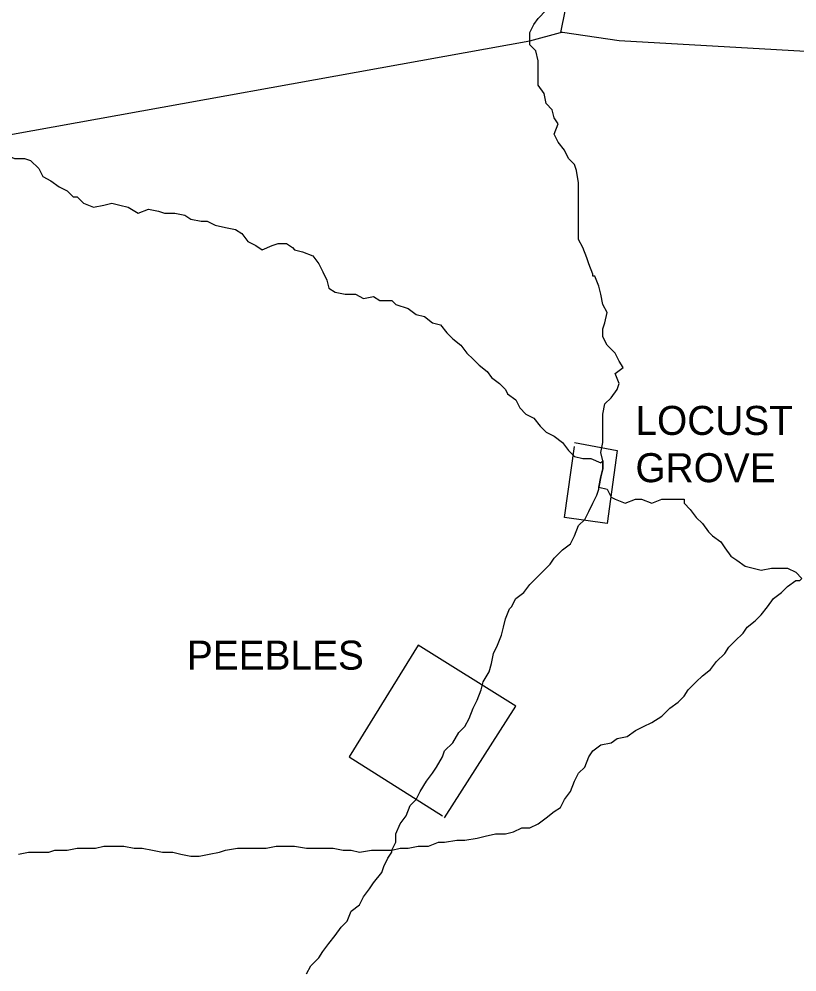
# Model space of a CAD drawing. Extents: x 0 to 34, y 0 to 22.
# Drawn here: x 4.319 to 4.841, y 17.195 to 17.836 of the extents above; entities that cross this region are included whole.
import ezdxf

# ---------------------------------------------------------------- set-up
doc = ezdxf.new("R2010")
doc.units = 0
doc.layers.add('Default', color=7, linetype='Continuous')

msp = doc.modelspace()

# ---------------------------------------------------------------- linework, layer by layer
at = {"layer": 'Default'}
for points in [[(4.80243, 18.46879), (4.77789, 18.33653), (4.75744, 18.21928), (4.74381, 18.1402), (4.72881, 18.05976), (4.71245, 17.97386), (4.68245, 17.82661)], [(4.662, 17.82116), (4.662, 17.82661), (4.66473, 17.83207), (4.66745, 17.83616), (4.67291, 17.84161), (4.677, 17.84707), (4.68245, 17.85116), (4.68245, 17.85661), (4.67972, 17.86206), (4.68245, 17.86752), (4.67836, 17.87297), (4.67836, 17.87979), (4.68109, 17.88524), (4.68245, 17.89206), (4.68245, 17.90024), (4.68245, 17.90433), (4.68245, 17.90433)], [(3.6667, 17.67937), (3.71715, 17.67664), (3.88212, 17.67118), (3.97347, 17.69027), (4.28433, 17.75299), (4.662, 17.82116), (4.68245, 17.82661)], [(4.70427, 17.66437), (4.70154, 17.67118), (4.70018, 17.67528), (4.69745, 17.68209), (4.69472, 17.68755), (4.69472, 17.69436), (4.69472, 17.70118), (4.69472, 17.708), (4.69472, 17.71345), (4.69472, 17.72027), (4.69472, 17.72572), (4.69336, 17.7339), (4.692, 17.73799), (4.68791, 17.74208), (4.68518, 17.74754), (4.68109, 17.75299), (4.67836, 17.75844), (4.68109, 17.76526), (4.67836, 17.76935), (4.677, 17.7748), (4.67291, 17.7789), (4.67154, 17.78571), (4.66745, 17.79117), (4.66745, 17.79526), (4.66745, 17.80207), (4.66745, 17.80753), (4.66609, 17.81434), (4.662, 17.81843), (4.662, 17.8198), (4.662, 17.82116)], [(4.93332, 17.80889), (4.72199, 17.82116), (4.68382, 17.82661), (4.68245, 17.82661)], [(4.2857, 17.75163), (4.29115, 17.75026), (4.29797, 17.7489), (4.30342, 17.74617), (4.30887, 17.74481), (4.31569, 17.74208), (4.32251, 17.74208), (4.3266, 17.74072), (4.33205, 17.73527), (4.33478, 17.72981), (4.34023, 17.72709), (4.34569, 17.72299), (4.35114, 17.72027), (4.35523, 17.71618), (4.35796, 17.71618)], [(4.35796, 17.71618), (4.36205, 17.71209), (4.36886, 17.70936), (4.37568, 17.71072), (4.38114, 17.71209), (4.38659, 17.71072), (4.39204, 17.70936), (4.39886, 17.70527), (4.40568, 17.708), (4.41249, 17.70663), (4.41658, 17.70527), (4.4234, 17.70527), (4.43022, 17.70391), (4.43431, 17.70118), (4.44113, 17.69982), (4.44522, 17.69982)], [(4.44522, 17.69982), (4.45067, 17.69709), (4.45749, 17.69573), (4.4643, 17.69436), (4.46839, 17.69164), (4.47248, 17.68618), (4.47794, 17.68346), (4.48203, 17.68073), (4.48885, 17.68346), (4.49294, 17.68482), (4.49839, 17.68482), (4.50248, 17.68209), (4.50384, 17.68073)], [(4.50384, 17.68073), (4.5093, 17.67937), (4.51611, 17.67664), (4.5202, 17.67118), (4.52293, 17.66573), (4.52566, 17.66028), (4.52702, 17.65482), (4.53111, 17.6521), (4.53793, 17.65073), (4.54475, 17.65073), (4.5502, 17.64801), (4.55702, 17.64937), (4.56111, 17.64664), (4.56247, 17.64664), (4.56247, 17.64664)], [(4.71108, 17.53893), (4.70972, 17.54439), (4.71108, 17.5512), (4.71108, 17.55666), (4.71108, 17.56484), (4.71108, 17.57029), (4.71245, 17.57711), (4.71654, 17.5812), (4.72063, 17.58665), (4.72199, 17.59074), (4.71926, 17.59756), (4.72472, 17.60165), (4.72199, 17.60574), (4.71926, 17.61119), (4.71381, 17.61665), (4.71108, 17.6221), (4.71108, 17.62756), (4.71245, 17.63165), (4.71381, 17.63846), (4.71108, 17.64392), (4.70972, 17.65073), (4.70836, 17.65619), (4.70563, 17.663), (4.70427, 17.663), (4.70427, 17.66437)], [(4.56247, 17.64664), (4.56929, 17.64664), (4.57201, 17.64392), (4.5802, 17.64119), (4.58565, 17.6371), (4.5911, 17.63574), (4.59656, 17.63165), (4.60201, 17.63028), (4.6061, 17.62483), (4.61019, 17.62074), (4.61564, 17.61665), (4.61973, 17.61119), (4.62382, 17.6071), (4.62791, 17.60301), (4.63337, 17.59892), (4.6361, 17.59483), (4.64155, 17.59074), (4.64564, 17.58665), (4.64564, 17.58665), (4.647, 17.58393)], [(4.647, 17.58393), (4.65246, 17.57984), (4.65518, 17.57438), (4.65927, 17.57029), (4.66473, 17.56756), (4.66882, 17.56211), (4.67291, 17.55802), (4.67836, 17.55529), (4.68382, 17.5512), (4.68791, 17.54575), (4.692, 17.54166), (4.69745, 17.5403), (4.7029, 17.5403), (4.70972, 17.53757), (4.71108, 17.53893)], [(4.692, 17.5512), (4.72063, 17.54575), (4.71381, 17.49667), (4.68518, 17.50076), (4.692, 17.54848)], [(4.71108, 17.53893), (4.71108, 17.53348), (4.70972, 17.52803), (4.70836, 17.52121)], [(4.70836, 17.52121), (4.70972, 17.52803), (4.71108, 17.53348), (4.71108, 17.53893)], [(4.64973, 17.44077), (4.65246, 17.44622), (4.65791, 17.45031), (4.662, 17.45576), (4.66609, 17.45985), (4.67018, 17.46394), (4.67563, 17.4694), (4.67836, 17.47349), (4.68382, 17.47894), (4.68927, 17.48303), (4.692, 17.48849), (4.69472, 17.4953), (4.69881, 17.49939), (4.70154, 17.50485), (4.70427, 17.5103), (4.70699, 17.51575), (4.70836, 17.51985), (4.70836, 17.52121)], [(4.70836, 17.52121), (4.71381, 17.51985), (4.71654, 17.51439), (4.71926, 17.51303), (4.72608, 17.5103), (4.7329, 17.51303), (4.73699, 17.51303), (4.74381, 17.5103), (4.75062, 17.51303), (4.75744, 17.51303), (4.76289, 17.51303), (4.76562, 17.51303), (4.76562, 17.5103)], [(4.76562, 17.5103), (4.76971, 17.50621), (4.7738, 17.50076), (4.77789, 17.49667), (4.78198, 17.49121), (4.78471, 17.48849), (4.79016, 17.4844), (4.79289, 17.48031), (4.79698, 17.47485), (4.80107, 17.47213), (4.80652, 17.46804), (4.81198, 17.46667), (4.81743, 17.46531), (4.82425, 17.46667), (4.83106, 17.46667), (4.83515, 17.46667), (4.84061, 17.46394), (4.8447, 17.45985), (4.8447, 17.45985)], [(4.75608, 17.3726), (4.76153, 17.37669), (4.76562, 17.38078), (4.76835, 17.38487), (4.7738, 17.39032), (4.77789, 17.39441), (4.78334, 17.3985), (4.78744, 17.40395), (4.79289, 17.40941), (4.79562, 17.4135), (4.79971, 17.41759), (4.80516, 17.42304), (4.80789, 17.42713), (4.81334, 17.43122), (4.81743, 17.43531), (4.82152, 17.44077), (4.82561, 17.44622), (4.83106, 17.45031), (4.83515, 17.4544), (4.84061, 17.45849), (4.84334, 17.45849), (4.8447, 17.45985)], [(4.60474, 17.34396), (4.61019, 17.34942), (4.61428, 17.35623), (4.61837, 17.36033), (4.6211, 17.36578), (4.62382, 17.3726), (4.62655, 17.37805), (4.62928, 17.38487), (4.63064, 17.39032), (4.63473, 17.39714), (4.6361, 17.40259), (4.63746, 17.40941), (4.64019, 17.41486), (4.64291, 17.42168), (4.64428, 17.42713), (4.64564, 17.43259), (4.64837, 17.4394), (4.64973, 17.44077)], [(4.60474, 17.29897), (4.65246, 17.37396), (4.58701, 17.41486), (4.54066, 17.33987), (4.60337, 17.30033)], [(4.65109, 17.28943), (4.65655, 17.29215), (4.662, 17.29215), (4.66745, 17.29488), (4.67291, 17.29897), (4.67836, 17.30306), (4.68245, 17.30579), (4.68518, 17.31124), (4.68927, 17.3167), (4.692, 17.32351), (4.69472, 17.32897), (4.69881, 17.33306), (4.70154, 17.33987), (4.70427, 17.34396), (4.70972, 17.34805), (4.71654, 17.34942), (4.72063, 17.35214), (4.72744, 17.35351), (4.7329, 17.3576), (4.73835, 17.36033), (4.74381, 17.36305), (4.75062, 17.36714), (4.75335, 17.36987), (4.75608, 17.3726), (4.75608, 17.3726)], [(4.56929, 17.27716), (4.57201, 17.28261), (4.57201, 17.28806), (4.57474, 17.29488), (4.57883, 17.30033), (4.58156, 17.30715), (4.58565, 17.31124), (4.58838, 17.3167), (4.59247, 17.32351), (4.59656, 17.32897), (4.59928, 17.33306), (4.60337, 17.33987), (4.60474, 17.34396), (4.60474, 17.34396)], [(4.56929, 17.27716), (4.57474, 17.27852), (4.5802, 17.27852), (4.58701, 17.27988), (4.59383, 17.27988), (4.60065, 17.28261), (4.60474, 17.28261), (4.61292, 17.28397), (4.61837, 17.28397), (4.62655, 17.28534), (4.63201, 17.2867), (4.63882, 17.28806), (4.64564, 17.28806), (4.65109, 17.28943)], [(4.31842, 17.27443), (4.32524, 17.27579), (4.33205, 17.27579), (4.33887, 17.27579), (4.34296, 17.27716), (4.35114, 17.27716), (4.35796, 17.27852), (4.36477, 17.27852), (4.37023, 17.27852), (4.37568, 17.27988), (4.3825, 17.27988), (4.38932, 17.27988), (4.39613, 17.27852), (4.40159, 17.27852), (4.4084, 17.27716), (4.41522, 17.27579), (4.42204, 17.27579), (4.42749, 17.27443), (4.43431, 17.27307), (4.43976, 17.27307), (4.44658, 17.27443), (4.4534, 17.27579), (4.45749, 17.27716), (4.46567, 17.27852), (4.47112, 17.27852), (4.4793, 17.27852), (4.48476, 17.27852), (4.49157, 17.27988), (4.49839, 17.27988), (4.50384, 17.27988), (4.51202, 17.27852), (4.51611, 17.27852), (4.52293, 17.27852), (4.52975, 17.27852), (4.53657, 17.27716), (4.54202, 17.27716), (4.54747, 17.27579), (4.55565, 17.27716), (4.56247, 17.27716), (4.56929, 17.27716), (4.56929, 17.27716)], [(4.51202, 17.19399), (4.51475, 17.19944), (4.5202, 17.2049), (4.52293, 17.20899), (4.52702, 17.21444), (4.53111, 17.21989), (4.5352, 17.22535), (4.53929, 17.22944), (4.54202, 17.23625), (4.54747, 17.24034), (4.5502, 17.2458), (4.55429, 17.25125), (4.55702, 17.25534), (4.56247, 17.26216), (4.56383, 17.26625), (4.56656, 17.2717), (4.56929, 17.27579), (4.56929, 17.27716)]]:
    msp.add_lwpolyline(points, dxfattribs=at)

# ---------------------------------------------------------------- texts
for s, p in [('LOCUST', (4.7329, 17.55624)), ('GROVE', (4.7329, 17.52447)), ('PEEBLES', (4.43158, 17.3985))]:
    msp.add_text(s, height=0.019502, dxfattribs=at).set_placement(p)

doc.saveas('drawing.dxf')
